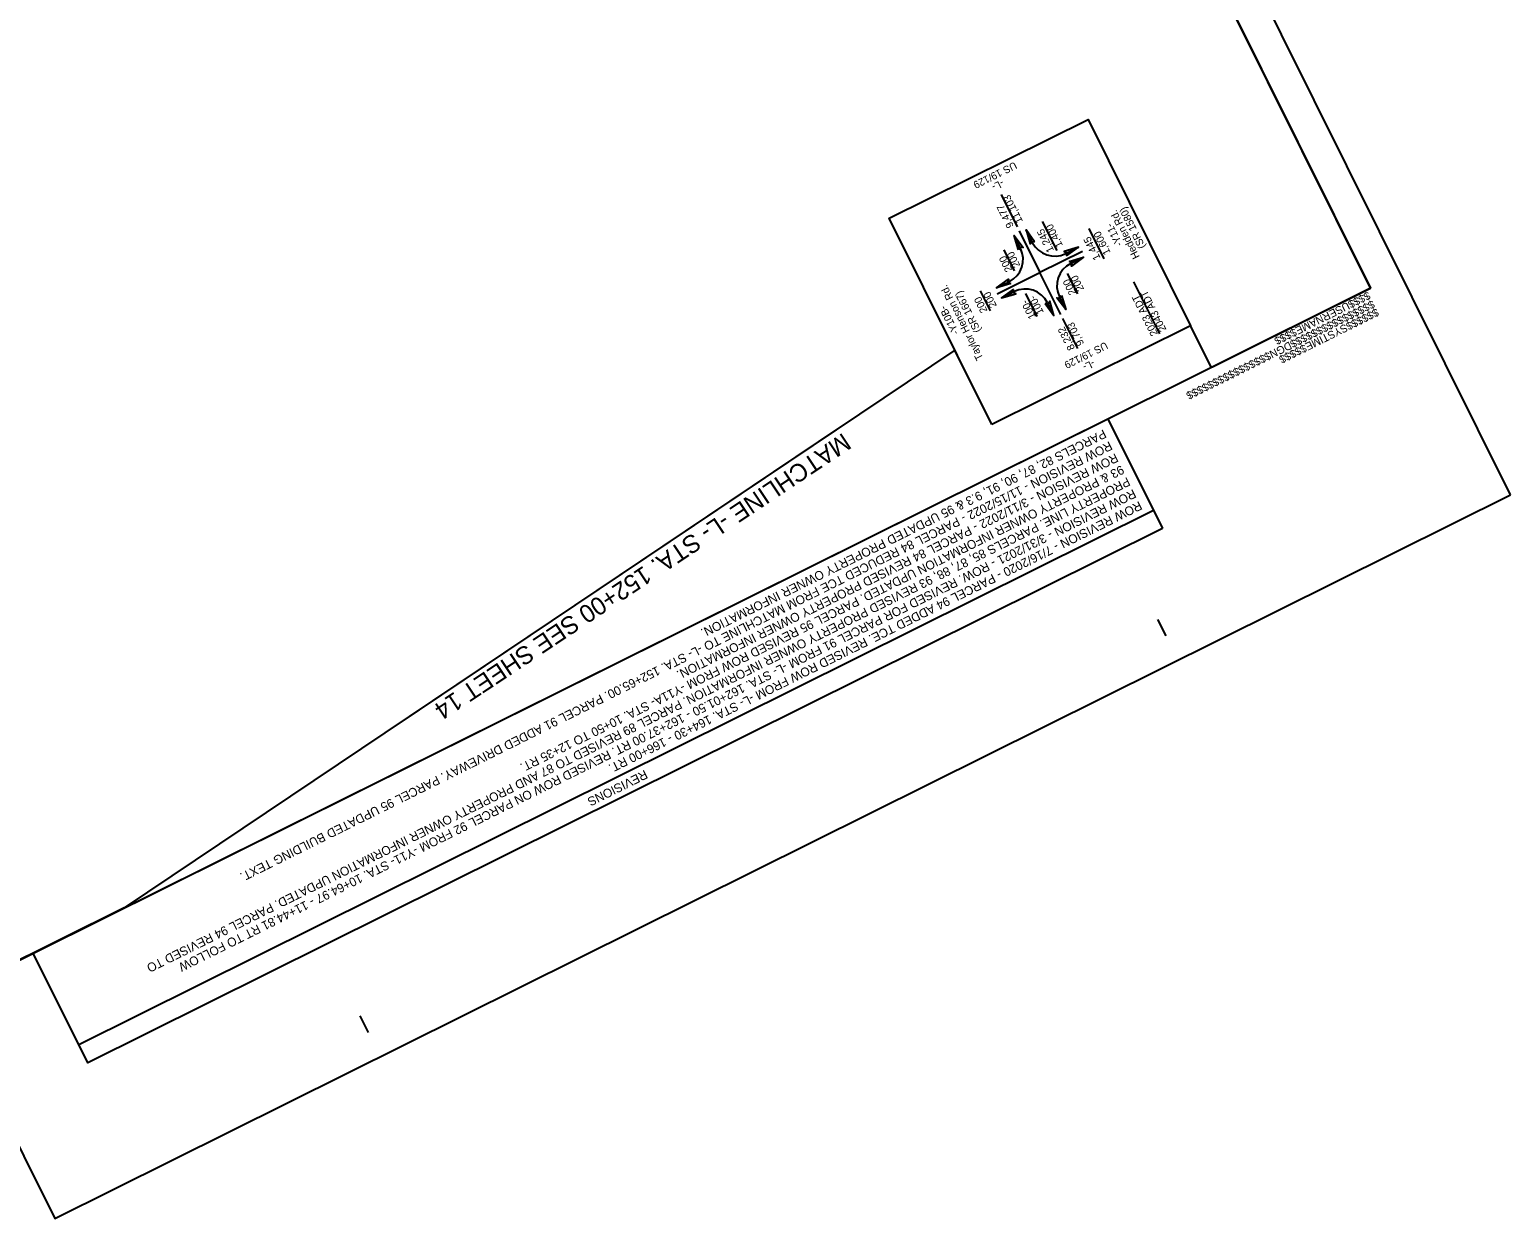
# Model space of a CAD drawing. Extents: x 475112 to 476842, y 500772 to 502767.
# Drawn here: x 475845 to 476842, y 500772 to 501573 of the extents above; entities that cross this region are included whole.
import ezdxf

# ---------------------------------------------------------------- set-up
doc = ezdxf.new("R2010")
doc.units = 0
for name, color, linetype in [('Matchline', 7, 'Continuous'), ('Matchline Text', 7, 'Continuous'), ('Prop DSN Text', 7, 'Continuous'), ('Prop PHM Traffic Signal CELL', 7, 'Continuous'), ('Sheet Block Revision CELL', 7, 'Continuous'), ('Sheet Clip Boundary CELL', 7, 'Continuous'), ('Sheet Plan CELL', 7, 'Continuous'), ('Sheet Plot Border Outside CELL', 7, 'Continuous')]:
    doc.layers.add(name, color=color, linetype=linetype)

msp = doc.modelspace()

# ---------------------------------------------------------------- linework, layer by layer
at = {"layer": 'Matchline'}
msp.add_line((476390.89, 501305.27), (476092.05, 501104.54), dxfattribs=at)
at = {"layer": 'Prop DSN Text'}
for p, q in [((476553.95, 501423.44), (476525.19, 501409.14)), ((476542.52, 501421.96), (476551.05, 501426.2)), ((476545.87, 501415.23), (476554.4, 501419.47)), ((476496.44, 501394.84), (476525.19, 501409.14)), ((476495.97, 501398.81), (476504.5, 501403.04)), ((476499.3, 501392.08), (476507.83, 501396.32))]:
    msp.add_line(p, q, dxfattribs=at)
for points in [[(476521.62, 501429.94), (476515.8, 501438.02), (476518.58, 501428.43), (476519.62, 501430.34)], [(476510.76, 501424.54), (476507.84, 501434.06), (476513.8, 501426.05), (476511.65, 501426.38)], [(476542.99, 501420.38), (476551.07, 501426.21), (476541.48, 501423.42), (476543.39, 501422.38)], [(476544.9, 501416.55), (476554.41, 501419.47), (476546.41, 501413.51), (476546.73, 501415.66)], [(476505.48, 501401.73), (476495.97, 501398.81), (476503.98, 501404.77), (476503.65, 501402.62)], [(476507.39, 501397.89), (476499.32, 501392.07), (476508.91, 501394.86), (476506.99, 501395.9)], [(476528.77, 501388.34), (476534.59, 501380.26), (476531.8, 501389.85), (476530.76, 501387.94)], [(476539.62, 501393.74), (476542.55, 501384.22), (476536.58, 501392.23), (476538.74, 501391.9)]]:
    msp.add_lwpolyline(points, close=True, dxfattribs=at)
for centre, start, end in [((476535.06, 501436.97), 206.48575, 296.48573), ((476497.05, 501418.07), 296.39558, 26.39557), ((476553.34, 501400.21), 116.39558, 206.39557), ((476515.32, 501381.31), 26.48575, 116.48573)]:
    msp.add_arc(centre, 16.77, start, end, dxfattribs=at)
at = {"layer": 'Prop PHM Traffic Signal CELL'}
for p, q in [((476499, 501461.71), (476509.76, 501440.08)), ((476520.05, 501429.49), (476515.81, 501438.02)), ((476526.71, 501443.6), (476536.46, 501423.99)), ((476558.1, 501438.95), (476568.32, 501418.41)), ((476512.03, 501425.6), (476507.8, 501434.13)), ((476511.19, 501437.29), (476525.19, 501409.14)), ((476511.19, 501437.29), (476525.19, 501409.14)), ((476500.86, 501424.48), (476507.88, 501410.37)), ((476539.19, 501380.99), (476525.19, 501409.14)), ((476539.19, 501380.99), (476525.19, 501409.14)), ((476550.6, 501394.82), (476543.8, 501408.49)), ((476588.2, 501402.95), (476605.62, 501367.92)), ((476484.88, 501396.95), (476491.62, 501383.41)), ((476523.29, 501379.62), (476515.61, 501395.07)), ((476534.57, 501380.26), (476530.34, 501388.79)), ((476542.55, 501384.22), (476538.31, 501392.76)), ((476550.63, 501358.1), (476540.63, 501378.21))]:
    msp.add_line(p, q, dxfattribs=at)
msp.add_lwpolyline([(476492.77, 501306.72), (476423.63, 501445.75), (476557.57, 501512.35), (476626.7, 501373.33)], close=True, dxfattribs=at)
at = {"layer": 'Sheet Block Revision CELL'}
msp.add_line((476601.69, 501248.86), (475877.74, 500888.84), dxfattribs=at)
msp.add_lwpolyline([(476607.74, 501236.73), (475883.78, 500876.72), (475846.99, 500950.64), (476570.94, 501310.66)], close=True, dxfattribs=at)
at = {"layer": 'Sheet Clip Boundary CELL'}
for p, q in [((476239.08, 502421.53), (476747.78, 501398.6)), ((476747.78, 501398.6), (476640.63, 501345.31)), ((476626.7, 501373.33), (476492.77, 501306.72)), ((476640.63, 501345.31), (476626.7, 501373.33)), ((476467.8, 501356.93), (475908.35, 500981.16)), ((476492.77, 501306.72), (476467.8, 501356.93)), ((475908.35, 500981.16), (475807.62, 500931.06))]:
    msp.add_line(p, q, dxfattribs=at)
at = {"layer": 'Sheet Plan CELL'}
for p, q in [((476747.78, 501398.6), (476747.78, 501398.6)), ((476610.2, 501164.36), (476604.65, 501175.56)), ((476072.99, 500897.18), (476067.39, 500908.37))]:
    msp.add_line(p, q, dxfattribs=at)
msp.add_lwpolyline([(475139.69, 502274.19), (475807.62, 500931.06), (476747.78, 501398.6), (476079.87, 502741.7)], close=True, dxfattribs=at)
at = {"layer": 'Sheet Plot Border Outside CELL'}
msp.add_lwpolyline([(476842.07, 501259.55), (476092.46, 502766.95), (475112, 502279.37), (475861.61, 500771.98)], close=True, dxfattribs=at)

# ---------------------------------------------------------------- texts
at = {"layer": 'Matchline Text'}
msp.add_text('MATCHLINE -L- STA. 152+00 SEE SHEET 14', height=12, rotation=213.68977, dxfattribs=at).set_placement((476392.48, 501301.58))
at = {"layer": 'Prop PHM Traffic Signal CELL'}
for s, rotation, p in [('US 19/129', 206.44074, (476508.06, 501484.04)), ('-L-', 206.44074, (476499.49, 501472.03)), ('11,103', 116.44061, (476513.81, 501443.73)), ('9,477', 116.44061, (476507.69, 501440.62)), ('Hedden Rd. ', 116.44061, (476592.49, 501419.83)), ('(SR 1580)', 116.44061, (476596.42, 501426.65)), ('1,245', 116.35049, (476534.78, 501424.16)), ('1,400', 116.35049, (476540.75, 501427.44)), ('-Y11-', 116.44061, (476580.97, 501428.26)), ('1,445', 116.44061, (476566.17, 501419)), ('1,600', 116.44061, (476572.96, 501422.6)), ('200', 116.44061, (476506.77, 501411.04)), ('200', 116.44061, (476512.06, 501413.91)), ('Taylor Henson Rd.', 116.44061, (476487.12, 501351.52)), ('200', 116.53082, (476549.76, 501395.41)), ('200', 116.53082, (476555.07, 501397.97)), ('(SR 1667)', 116.44061, (476485.61, 501370.12)), ('200', 116.44061, (476489.99, 501383.49)), ('200', 116.44061, (476496.23, 501386.87)), ('100-', 116.4407, (476522.57, 501379.34)), ('100-', 116.4407, (476527.87, 501382.37)), ('2023 ADT', 116.44061, (476604.74, 501367.93)), ('2043 ADT', 116.44061, (476610.48, 501370.78)), ('-Y10B-', 116.44061, (476470.79, 501368.78)), ('8,232', 116.4407, (476548.9, 501358.21)), ('9,703', 116.4407, (476555.09, 501361.26)), ('US 19/129', 206.44074, (476569.33, 501362.7)), ('-L-', 206.44074, (476560.76, 501350.69))]:
    msp.add_text(s, height=5, rotation=rotation, dxfattribs=at).set_placement(p)
at = {"layer": 'Sheet Block Revision CELL'}
for s, p in [('PARCELS 82, 87, 90, 91, 9.3 & 95 UPDATED PROPERTY OWNER INFORMATION. ', (476567.95, 501303.74)), ('ROW REVISION - 11/15/2022 - PARCEL 84 REDUCED TCE FROM MATCHLINE TO -L- STA. 152+65.00. PARCEL 91 ADDED DRIVEWAY. PARCEL 95 UPDATED BUILDING TEXT. ', (476571.96, 501295.68)), ('93 & PROPERTY OWNER INFORMATION UPDATED. PARCEL 95 REVISED ROW FROM -Y11A- STA. 10+50 TO 12+35 RT. ', (476579.97, 501279.56)), ('ROW REVISION - 3/11/2022 - PARCEL 84 REVISED PROPERTY OWNER INFORMATION.', (476575.97, 501287.62)), ('PROPERTY LINE. PARCELS 85, 87, 88, 93 REVISED PROPERTY OWNER INFORMATION. PARCEL 89 REVISED TO 87 AND PROPERTY OWNER INFORMATION UPDATED. PARCEL 94 REVISED TO ', (476583.98, 501271.5)), ('ROW REVISION - 3/31/2021 - ROW. REVISED FOR PARCEL 91 FROM -L- STA. 162+01.50 - 162+37.00 RT. REVISED ROW ON PARCEL 92 FROM -Y11- STA. 10+64.97 - 11+44.81 RT TO FOLLOW ', (476587.99, 501263.44)), ('ROW REVISION - 7/16/2020 - PARCEL 94 ADDED TCE. REVISED ROW FROM -L- STA. 164+30 - 166+00 RT.', (476592, 501255.38)), ('REVISIONS', (476258.95, 501074.28))]:
    msp.add_text(s, height=6, rotation=206.44074, dxfattribs=at).set_placement(p)
at = {"layer": 'Sheet Plan CELL'}
for s, p in [('$$$$$$$$$$$$$$$$DGN$$$$$$$$$$$$$$$$', (476749.07, 501390.71)), ('$$$$USERNAME$$$$', (476746.14, 501396.57)), ('$$$$$$SYSTIME$$$$$', (476751.79, 501385.28))]:
    msp.add_text(s, height=5.25, rotation=206.44074, dxfattribs=at).set_placement(p)

doc.saveas('drawing.dxf')
